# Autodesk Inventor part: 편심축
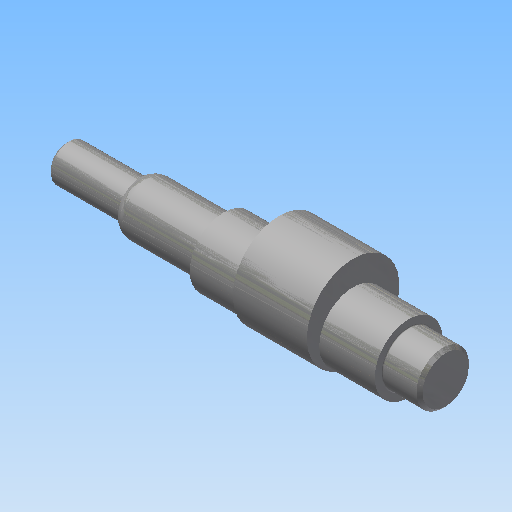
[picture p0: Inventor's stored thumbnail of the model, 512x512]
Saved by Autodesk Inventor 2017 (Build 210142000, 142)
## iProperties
Created: 2020-07
Part Number: 편심축
Material: 강철, 연강
Document SubType Name: Modeling
Designer: mduedu
Density: 7.86 g/cm^3
Mass: 329.439 g
Surface Area: 91.9337 cm^2
Volume: 41.9134 cm^3
Appearance: 강철
Author: mduedu
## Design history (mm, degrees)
sketch "스케치1"
  geometry: L1 (0, 0)-(24, 0); L2 (24, 0)-(24, 6); L3 (24, 6)-(0, 6); L4 (0, 6)-(0, 0); L5 (24, 0)-(51, 0); L6 (51, 0)-(51, 8.5); L7 (51, 8.5)-(24, 8.5); L8 (24, 8.5)-(24, 0); L9 (51, 0)-(111, 0); L10 (111, 0)-(111, 11); L11 (111, 11)-(51, 11); L12 (51, 11)-(51, 0); L13 (111, 0)-(123, 0); L14 (123, 0)-(123, 8.5); L15 (123, 8.5)-(111, 8.5); L16 (111, 8.5)-(111, 0)
  constraints: 32 end point, 8 parallel, 4 horizontal, 4 perpendicular
  dimensions: "d0" = 123 distance between parallel lines of L14 L4; "d2" = 12 distance of L14.end L15.end; "d3" = 60 distance of L10.end L11.end; "d4" = 99 distance between parallel lines of L8 L14; "d5" = 24 distance of L2.end L3.end (derived); "d6" = 12 diameter of L3 L1; "d7" = 17 diameter of L7 L5; "d8" = 22 diameter of L11 L9; "d9" = 17 diameter of L15 L13
revolve "회전1" sketch "스케치1" stored, may be unused: angle "d10" = 90 deg
node "작업 평면1"
sketch "스케치2"
  geometry: C1 r 15 at (-4, 0); C2 r 11 at (0, 0) reference; 1 further point
  constraints: 1 centre point, 1 horizontal alignment, 1 tangent
  dimensions: "d12" = 4 distance of point (0, 0) C1.centre
extrude "돌출1" join sketch "스케치2" distance "d13" = 24; taper "d14" = 0 deg
node "작업 평면2"
sketch "스케치3" dims "d17" = 12
  geometry: L1 (5, -2)-(-3, -2); L2 (-3, -2)-(-3, 2); L3 (-3, 2)-(5, 2); L4 (5, 2)-(5, -2); L5 (-12, 8.5)-(-12, -8.5); L6 (-12, 8.5)-(-12, -8.5) reference; L7 (12, 6)-(12, -6) reference; 5 further points
  constraints: 10 end point, 4 midpoint, 2 horizontal alignment, 2 parallel, 2 vertical alignment, 1 coincident, 1 collinear, 1 horizontal, 1 perpendicular, 4 other
  dimensions: "d15" = 7 dimension on L5; "d16" = 4 distance between parallel lines of L3 L1
extrude "돌출2" cut sketch "스케치3" distance "d18" = 2.5; taper "d19" = 0 deg
hole "구멍1" diameter "d22" = 3.242; stored, may be unused: countersink angle "d26" = 90 deg, drill point angle "d28" = 118 deg; dims "d20" = 10, "d21" = 10, "d23" = 8, "d24" = 4, "d25" = 2, "d27" = 10
sketch "스케치4"
  geometry: L1 (10, 1.621)-(0, 1.621) reference; L2 (0, 0)-(2, 0); L3 (2, 0)-(2, 1.621); L4 (0, 2.776)-(0, 0); L5 (0, 2.776)-(2, 1.621)
  constraints: 8 end point, 1 horizontal, 1 parallel, 1 perpendicular, 1 point on line
  dimensions: "d29" = 2 horizontal distance of L4.start L3.end; "d31" = 30 deg angle of L5 L2
revolve "회전2" sketch "스케치4" stored, may be unused: angle "d33" = 90 deg
chamfer "모따기1" distance "d34" = 1; stored, may be unused: second distance "d35" = 2, angle "d36" = 45 deg
fillet "모깎기1" dims "d37" = 0.3
sketch "스케치5"
  geometry: L1 (24, -8.5)-(24, 8.5) reference; L2 (24, 8.5)-(50.7, 8.5) reference; L3 (24, 7.45)-(25.819, 8.5); L4 (0, 0)-(24, 0)
  constraints: 4 end point, 2 point on line, 1 midpoint
  dimensions: "d38" = 14.9 diameter of L3.start L4; "d39" = 30 deg angle of L3 L2
revolve "회전3" sketch "스케치5" stored, may be unused: angle "d40" = 90 deg
fillet "모깎기2" dims "d41" = 4, "d42" = 0.5
node "솔리드1"
